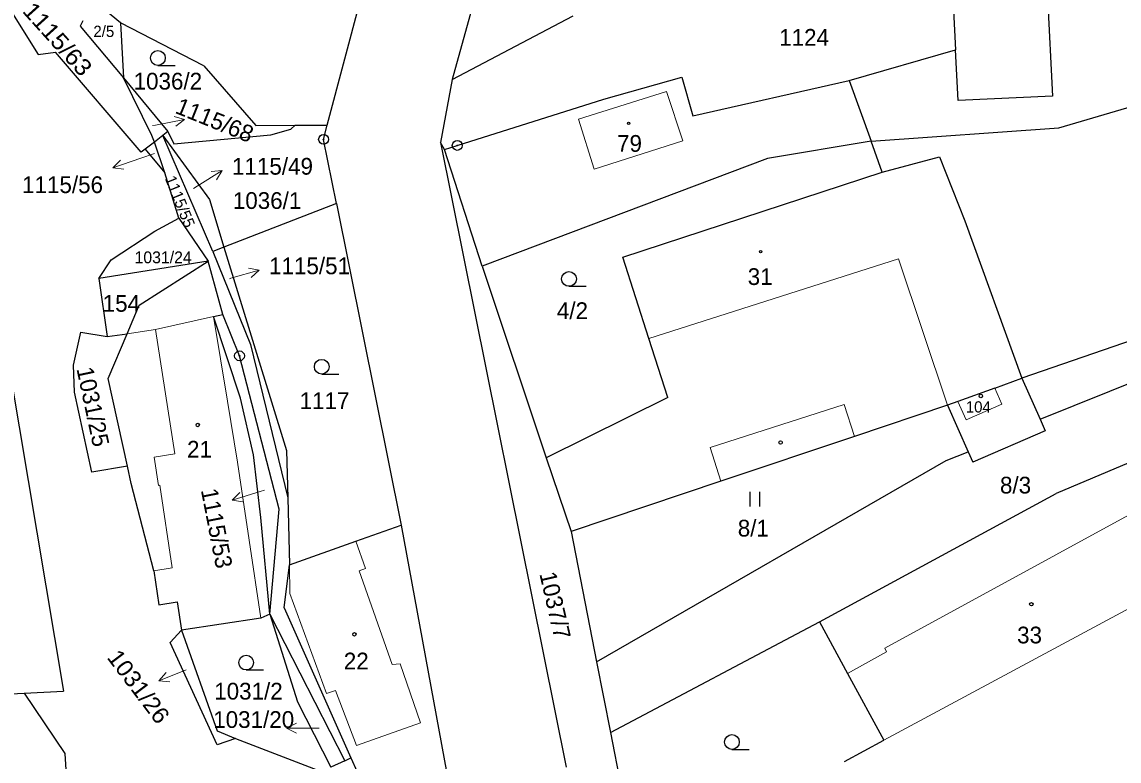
# Model space of a CAD drawing. Extents: x -618848 to -615803, y -1044450 to -1042254.
# Drawn here: x -617086 to -616974.7, y -1042969.1 to -1042894.1 of the extents above; entities that cross this region are included whole.
import ezdxf
from ezdxf.enums import TextEntityAlignment as Align

# ---------------------------------------------------------------- set-up
doc = ezdxf.new("R2010")
doc.units = 0
doc.header["$LTSCALE"] = 0.68
for name, color, linetype, lineweight in [('1', 7, 'Continuous', 25), ('3', 7, 'Continuous', 25), ('4', 7, 'Continuous', 13), ('5', 7, 'Continuous', 25), ('7', 7, 'Continuous', 13), ('8', 7, 'Continuous', 25)]:
    doc.layers.add(name, color=color, linetype=linetype, lineweight=lineweight)
doc.layers.add('2', color=7, linetype='Continuous')

msp = doc.modelspace()

# ---------------------------------------------------------------- linework, layer by layer
at = {"layer": '1'}
for p, q in [((-617031.54, -1042860.9), (-617042.35, -1042899.95)), ((-616982.6, -1042878.23), (-616981.43, -1042901.63)), ((-616992.16, -1042878.67), (-616991.27, -1042896.95)), ((-617055.02, -1042904.58), (-617048.41, -1042879.63)), ((-617088.75, -1042890.36), (-617084.37, -1042897.42)), ((-617076.01, -1042894.21), (-617078.09, -1042892.47)), ((-617079.84, -1042894.01), (-617080.1, -1042894.53)), ((-617042.35, -1042899.95), (-617030.08, -1042893.5)), ((-617080.1, -1042894.53), (-617075.71, -1042899.8)), ((-617076.01, -1042894.21), (-617075.71, -1042899.8)), ((-617067.55, -1042898.57), (-617076.01, -1042894.21)), ((-616980.78, -1042904.85), (-616951.23, -1042896.19)), ((-617084.37, -1042897.42), (-617082.59, -1042897.18)), ((-617073.92, -1042907.34), (-617082.59, -1042897.18)), ((-617002.05, -1042900.06), (-616991.27, -1042896.95)), ((-616991.01, -1042902.07), (-616991.27, -1042896.95)), ((-617067.55, -1042898.57), (-617062.26, -1042904.62)), ((-617072.82, -1042905.63), (-617075.71, -1042899.8)), ((-617075.71, -1042899.8), (-617071.19, -1042905.24)), ((-617042.35, -1042899.95), (-617043.53, -1042906.35)), ((-617026.96, -1042901.94), (-617019.05, -1042899.72)), ((-617019.05, -1042899.72), (-617017.91, -1042903.64)), ((-617017.91, -1042903.64), (-617002.05, -1042900.06)), ((-617002.05, -1042900.06), (-616999.83, -1042906.23)), ((-616981.43, -1042901.63), (-616991.01, -1042902.07)), ((-617062.26, -1042904.62), (-617058.27, -1042904.6)), ((-617060.75, -1042905.57), (-617058.72, -1042905)), ((-617058.72, -1042905), (-617058.27, -1042904.6)), ((-617058.27, -1042904.6), (-617055.02, -1042904.58)), ((-617055.4, -1042906.03), (-617055.02, -1042904.58)), ((-616999.83, -1042906.23), (-616980.78, -1042904.85)), ((-617072.56, -1042906.3), (-617072.82, -1042905.63)), ((-617071.7, -1042905.64), (-617072.56, -1042906.3)), ((-617071.19, -1042905.24), (-617071.7, -1042905.64)), ((-617066.62, -1042917.41), (-617071.7, -1042905.64)), ((-617071.7, -1042905.64), (-617066.99, -1042912.15)), ((-617071.19, -1042905.24), (-617070.59, -1042906.48)), ((-617070.59, -1042906.48), (-617060.75, -1042905.57)), ((-617054.08, -1042912.56), (-617055.4, -1042906.03)), ((-616999.83, -1042906.23), (-617010.35, -1042907.97)), ((-616998.7, -1042909.36), (-616999.83, -1042906.23)), ((-617073.5, -1042907.02), (-617073.92, -1042907.34)), ((-617072.56, -1042906.3), (-617073.5, -1042907.02)), ((-617073.5, -1042907.02), (-617071.51, -1042909.44)), ((-617071.51, -1042909.44), (-617072.56, -1042906.3)), ((-617043.53, -1042906.35), (-617030.78, -1042969.76)), ((-617043.14, -1042907.07), (-617043.53, -1042906.35)), ((-617039.31, -1042918.92), (-617043.14, -1042907.07)), ((-617010.35, -1042907.97), (-617039.31, -1042918.92)), ((-616998.7, -1042909.36), (-616992.89, -1042907.8)), ((-616992.89, -1042907.8), (-616990.31, -1042914.3)), ((-617070.1, -1042914.02), (-617071.51, -1042909.44)), ((-617025.04, -1042917.99), (-616998.7, -1042909.36)), ((-617066.99, -1042912.15), (-617065.51, -1042916.98)), ((-617054.08, -1042912.56), (-617065.51, -1042916.98)), ((-617054.08, -1042912.56), (-617047.51, -1042945.2)), ((-617072.52, -1042915.36), (-617070.1, -1042914.02)), ((-617070.1, -1042914.02), (-617067.1, -1042918.4)), ((-616990.31, -1042914.3), (-616984.53, -1042930.29)), ((-617076.96, -1042918.26), (-617072.52, -1042915.36)), ((-617065.51, -1042916.98), (-617066.62, -1042917.41)), ((-617065.51, -1042916.98), (-617059.16, -1042937.63)), ((-617078.19, -1042920.15), (-617076.96, -1042918.26)), ((-617067.1, -1042918.4), (-617078.19, -1042920.15)), ((-617074.12, -1042922.88), (-617067.1, -1042918.4)), ((-617065.62, -1042923.82), (-617067.1, -1042918.4)), ((-617066.62, -1042917.41), (-617062.8, -1042926.85)), ((-617022.4, -1042926.25), (-617025.04, -1042917.99)), ((-616982.68, -1042934.45), (-616942.75, -1042918.37)), ((-617039.31, -1042918.92), (-617032.79, -1042938.36)), ((-617078.19, -1042920.15), (-617077.37, -1042926.05)), ((-617075.33, -1042925.76), (-617074.12, -1042922.88)), ((-617066.56, -1042924.01), (-617065.62, -1042923.82)), ((-617063.82, -1042932.31), (-617066.56, -1042924.01)), ((-617063.93, -1042928.01), (-617065.62, -1042923.82)), ((-616965.61, -1042923.76), (-616984.53, -1042930.29)), ((-617088.08, -1042924.53), (-617081.79, -1042962.05)), ((-616940.22, -1042924.67), (-616981.06, -1042942)), ((-617080.77, -1042928.94), (-617080.03, -1042925.59)), ((-617080.03, -1042925.59), (-617077.37, -1042926.05)), ((-617077.37, -1042926.05), (-617075.33, -1042925.76)), ((-617020.47, -1042932.25), (-617022.4, -1042926.25)), ((-617062.8, -1042926.85), (-617059.04, -1042942.42)), ((-617059.9, -1042943.56), (-617063.93, -1042928.01)), ((-617080.66, -1042931.69), (-617080.77, -1042928.94)), ((-616987.28, -1042931.29), (-616984.53, -1042930.29)), ((-616984.53, -1042930.29), (-616982.68, -1042934.45)), ((-617078.93, -1042939.81), (-617080.66, -1042931.69)), ((-616987.28, -1042931.29), (-616991.04, -1042932.66)), ((-617062.5, -1042938.06), (-617063.82, -1042932.31)), ((-617020.47, -1042932.25), (-617032.79, -1042938.36)), ((-616991.04, -1042932.66), (-616992.06, -1042933.03)), ((-616992.06, -1042933.03), (-617001.51, -1042936.2)), ((-616992.06, -1042933.03), (-616989.98, -1042937.74)), ((-616982.68, -1042934.45), (-616982.16, -1042935.61)), ((-617001.51, -1042936.2), (-617015.09, -1042940.75)), ((-616982.16, -1042935.61), (-616989.51, -1042938.82)), ((-617061.77, -1042944.41), (-617062.5, -1042938.06)), ((-617059.16, -1042937.63), (-617059.04, -1042942.42)), ((-617032.79, -1042938.36), (-617030.28, -1042945.85)), ((-616992.2, -1042938.65), (-616989.98, -1042937.74)), ((-616989.98, -1042937.74), (-616989.51, -1042938.82)), ((-617075.29, -1042939.22), (-617078.93, -1042939.81)), ((-617074.91, -1042940.96), (-617075.29, -1042939.22)), ((-617027.69, -1042959.09), (-616992.2, -1042938.65)), ((-617015.09, -1042940.75), (-617030.28, -1042945.85)), ((-617072.61, -1042949.82), (-617074.91, -1042940.96)), ((-617059.04, -1042942.42), (-617058.86, -1042949.24)), ((-617005.07, -1042955.02), (-616981.06, -1042942)), ((-617060.85, -1042954.25), (-617059.9, -1042943.56)), ((-617060.85, -1042954.25), (-617061.77, -1042944.41)), ((-617052.13, -1042946.84), (-617047.51, -1042945.2)), ((-617047.51, -1042945.2), (-617042.89, -1042970.41)), ((-617030.28, -1042945.85), (-617027.69, -1042959.09)), ((-617058.86, -1042949.24), (-617052.13, -1042946.84)), ((-617059.41, -1042953.6), (-617058.86, -1042949.24)), ((-617072.61, -1042949.82), (-617072.11, -1042953.28)), ((-617072.11, -1042953.28), (-617070.26, -1042952.99)), ((-617070.26, -1042952.99), (-617069.82, -1042955.87)), ((-617059.41, -1042953.6), (-617052.62, -1042968.82)), ((-617061.76, -1042954.65), (-617069.82, -1042955.87)), ((-617060.85, -1042954.25), (-617061.76, -1042954.65)), ((-617060.85, -1042954.25), (-617053.24, -1042969.11)), ((-617060.85, -1042954.25), (-617058.05, -1042963.13)), ((-617026.28, -1042966.26), (-617005.07, -1042955.02)), ((-617005.07, -1042955.02), (-617002.22, -1042960.25)), ((-617070.98, -1042957.12), (-617069.82, -1042955.87)), ((-617069.82, -1042955.87), (-617066.18, -1042966.08)), ((-617066.19, -1042967.5), (-617070.98, -1042957.12)), ((-617027.69, -1042959.09), (-617026.28, -1042966.26)), ((-617002.22, -1042960.25), (-616998.53, -1042967.03)), ((-617092.07, -1042962.57), (-617085.77, -1042962.25)), ((-617085.77, -1042962.25), (-617081.79, -1042962.05)), ((-617085.77, -1042962.25), (-617081.64, -1042968.39)), ((-617058.05, -1042963.13), (-617054.66, -1042969.77)), ((-617066.18, -1042966.08), (-617064.32, -1042966.86)), ((-617026.28, -1042966.26), (-617021.89, -1042988.71)), ((-617064.32, -1042966.86), (-617066.19, -1042967.5)), ((-617064.32, -1042966.86), (-617054.22, -1042970.74)), ((-617002.54, -1042969.19), (-616998.53, -1042967.03)), ((-617081.64, -1042968.39), (-617081.14, -1042976.85)), ((-617053.24, -1042969.11), (-617054.66, -1042969.77)), ((-617053.24, -1042969.11), (-617052.62, -1042968.82)), ((-617052.62, -1042968.82), (-617050.63, -1042973.29))]:
    msp.add_line(p, q, dxfattribs=at)
for points in [[(-617043.14, -1042907.07), (-617041.83, -1042906.65), (-617026.96, -1042901.94)], [(-617075.29, -1042939.22), (-617077.25, -1042930.32), (-617075.33, -1042925.76)]]:
    msp.add_lwpolyline(points, dxfattribs=at)
at = {"layer": '3'}
for p, q in [((-617072.213, -1042898.52), (-617070.463, -1042898.52)), ((-617030.493, -1042920.95), (-617028.743, -1042920.95)), ((-617055.583, -1042929.87), (-617053.833, -1042929.87)), ((-617012.111, -1042943.32), (-617012.111, -1042941.82)), ((-617011.11, -1042943.32), (-617011.11, -1042941.82)), ((-617063.253, -1042959.9), (-617061.503, -1042959.9)), ((-617013.953, -1042967.97), (-617012.203, -1042967.97))]:
    msp.add_line(p, q, dxfattribs=at)
for centre in [(-617072.2129, -1042897.7698), (-617030.4929, -1042920.1998), (-617055.5829, -1042929.1198), (-617063.2529, -1042959.1498), (-617013.9529, -1042967.2198)]:
    msp.add_circle(centre, 0.75, dxfattribs=at)
at = {"layer": '4'}
for p, q in [((-617020.58, -1042901.17), (-617029.53, -1042903.99)), ((-617018.95, -1042906.19), (-617020.58, -1042901.17)), ((-617029.53, -1042903.99), (-617027.93, -1042909.05)), ((-617027.93, -1042909.05), (-617018.95, -1042906.19)), ((-616997.06, -1042918.15), (-617022.4, -1042926.25)), ((-616997.06, -1042918.15), (-616992.06, -1042933.03)), ((-617072.44, -1042925.34), (-617066.56, -1042924.01)), ((-617065.15, -1042932.62), (-617066.56, -1042924.01)), ((-617075.33, -1042925.76), (-617072.44, -1042925.34)), ((-617072.44, -1042925.34), (-617070.49, -1042937.96)), ((-616986.56, -1042932.9), (-616987.28, -1042931.29)), ((-617065.15, -1042932.62), (-617064.14, -1042938.82)), ((-617016.15, -1042937.33), (-617002.55, -1042932.95)), ((-617002.55, -1042932.95), (-617001.51, -1042936.2)), ((-616991.04, -1042932.66), (-616990.19, -1042934.51)), ((-616990.19, -1042934.51), (-616986.56, -1042932.9)), ((-617016.15, -1042937.33), (-617015.09, -1042940.75)), ((-617070.49, -1042937.96), (-617072.6, -1042938.31)), ((-617072.6, -1042938.31), (-617072.15, -1042941.16)), ((-617064.14, -1042938.82), (-617061.76, -1042954.65)), ((-617072.15, -1042941.16), (-617072.02, -1042941.14)), ((-617072.02, -1042941.14), (-617070.76, -1042949.53)), ((-616969.98, -1042942.16), (-616998.45, -1042957.68)), ((-617051.15, -1042949.61), (-617052.13, -1042946.84)), ((-617070.76, -1042949.53), (-617072.61, -1042949.82)), ((-617058.86, -1042949.24), (-617058.82, -1042952.13)), ((-617051.15, -1042949.61), (-617051.8, -1042949.84)), ((-616998.53, -1042967.03), (-616965.96, -1042949.49)), ((-617048.42, -1042959.36), (-617051.8, -1042949.84)), ((-617058.82, -1042952.13), (-617055.09, -1042962.3)), ((-616998.25, -1042958.06), (-617002.22, -1042960.25)), ((-616998.45, -1042957.68), (-616998.25, -1042958.06)), ((-617047.64, -1042959.27), (-617048.42, -1042959.36)), ((-617045.56, -1042965.26), (-617047.64, -1042959.27)), ((-617055.09, -1042962.3), (-617054.19, -1042961.98)), ((-617054.19, -1042961.98), (-617052.06, -1042967.57)), ((-617052.06, -1042967.57), (-617045.56, -1042965.26))]:
    msp.add_line(p, q, dxfattribs=at)
at = {"layer": '5'}
for centre, radius in [((-617024.4346, -1042904.4194), 0.1172), ((-617011.0446, -1042917.4194), 0.1172), ((-616988.6968, -1042932.0892), 0.175), ((-617068.1668, -1042935.0292), 0.175), ((-617009.0168, -1042936.8092), 0.175), ((-616983.5668, -1042953.2292), 0.175), ((-617052.2668, -1042956.2792), 0.175)]:
    msp.add_circle(centre, radius, dxfattribs=at)
at = {"layer": '7'}
for p, q in [((-617069.494, -1042904.007), (-617070.573, -1042903.707)), ((-617076.777, -1042908.927), (-617075.668, -1042909.074)), ((-617065.685, -1042909.2), (-617066.8, -1042909.306)), ((-617061.925, -1042919.313), (-617063.026, -1042919.108)), ((-617064.69, -1042942.657), (-617063.586, -1042942.843)), ((-617072.112, -1042961.004), (-617070.996, -1042961.093)), ((-617059.151, -1042965.8), (-617058.15, -1042966.301))]:
    msp.add_line(p, q, dxfattribs=at)
for points in [[(-617072.76, -1042904.64), (-617072.44, -1042904.58), (-617069.494, -1042904.007), (-617070.382, -1042904.69)], [(-617072.55, -1042907.48), (-617073.94, -1042907.95), (-617076.777, -1042908.927), (-617075.994, -1042908.128)], [(-617068.6, -1042911.03), (-617068.23, -1042910.79), (-617065.685, -1042909.2), (-617066.269, -1042910.155)], [(-617064.96, -1042920.18), (-617064.81, -1042920.14), (-617061.925, -1042919.313), (-617062.75, -1042920.07)], [(-617061.4, -1042941.65), (-617061.82, -1042941.78), (-617064.69, -1042942.657), (-617063.879, -1042941.886)], [(-617069.33, -1042959.88), (-617072.112, -1042961.004), (-617071.372, -1042960.165)], [(-617055.83, -1042965.8), (-617056.15, -1042965.8), (-617059.151, -1042965.8), (-617058.15, -1042965.299)]]:
    msp.add_lwpolyline(points, dxfattribs=at)
at = {"layer": '8'}
for centre, radius in [((-617055.4, -1042906.0299), 0.5), ((-617055.4, -1042906.0299), 0.0303), ((-617041.83, -1042906.6499), 0.5), ((-617041.83, -1042906.6499), 0.0303), ((-617063.93, -1042928.0099), 0.5), ((-617063.93, -1042928.0099), 0.0303)]:
    msp.add_circle(centre, radius, dxfattribs=at)

# ---------------------------------------------------------------- texts
at = {"layer": '2', "width": 1.1}
msp.add_text('1115/63', height=1.7, rotation=312, dxfattribs=at).set_placement((-617086.046, -1042893.056))
at = {"layer": '2'}
for s, height, p in [('2/5', 1.14, (-617077.699, -1042895.635)), ('1124', 1.7, (-617006.63, -1042896.525)), ('1036/2', 1.7, (-617071.2, -1042900.975)), ('79', 1.7, (-617024.349, -1042907.295)), ('1036/1', 1.7, (-617061.13, -1042913.095)), ('1031/24', 1.2, (-617071.679, -1042918.61)), ('31', 1.7, (-617011.089, -1042920.815)), ('154', 1.7, (-617075.919, -1042923.535)), ('4/2', 1.7, (-617030.14, -1042924.275)), ('1117', 1.7, (-617055.3, -1042933.415)), ('104', 1.14, (-616988.95, -1042933.765)), ('21', 1.7, (-617067.989, -1042938.345)), ('8/3', 1.7, (-616985.17, -1042941.985)), ('8/1', 1.7, (-617011.78, -1042946.355)), ('33', 1.7, (-616983.749, -1042957.205)), ('22', 1.7, (-617052.079, -1042959.845)), ('1031/2', 1.7, (-617063.02, -1042962.905))]:
    msp.add_text(s, height=height, dxfattribs=at).set_placement(p, align=Align.CENTER)
msp.add_text('1115/68', height=1.7, rotation=338, dxfattribs=at).set_placement((-617070.569, -1042903.324))
for s, p in [('1115/49', (-617064.69, -1042909.615)), ('1115/51', (-617060.93, -1042919.725))]:
    msp.add_text(s, height=1.7, dxfattribs=at).set_placement(p)
for s, p in [('1115/56', (-617077.78, -1042911.485)), ('1031/20', (-617058.38, -1042965.785))]:
    msp.add_text(s, height=1.7, dxfattribs=at).set_placement(p, align=Align.RIGHT)
for s, height, rotation, p in [('1115/55', 1.14, 292, (-617070.4899, -1042912.555)), ('1031/25', 1.7, 282, (-617079.6261, -1042933.3483)), ('1037/7', 1.7, 283, (-617032.7208, -1042953.5228))]:
    msp.add_text(s, height=height, rotation=rotation, dxfattribs=at).set_placement(p, align=Align.CENTER)
msp.add_text('1115/53', height=1.7, rotation=281, dxfattribs=at).set_placement((-617066.2854, -1042949.7046), align=Align.RIGHT)
at = {"layer": '2', "width": 1.05}
msp.add_text('1031/26', height=1.7, rotation=307, dxfattribs=at).set_placement((-617074.8521, -1042962.0955), align=Align.CENTER)

doc.saveas('drawing.dxf')
